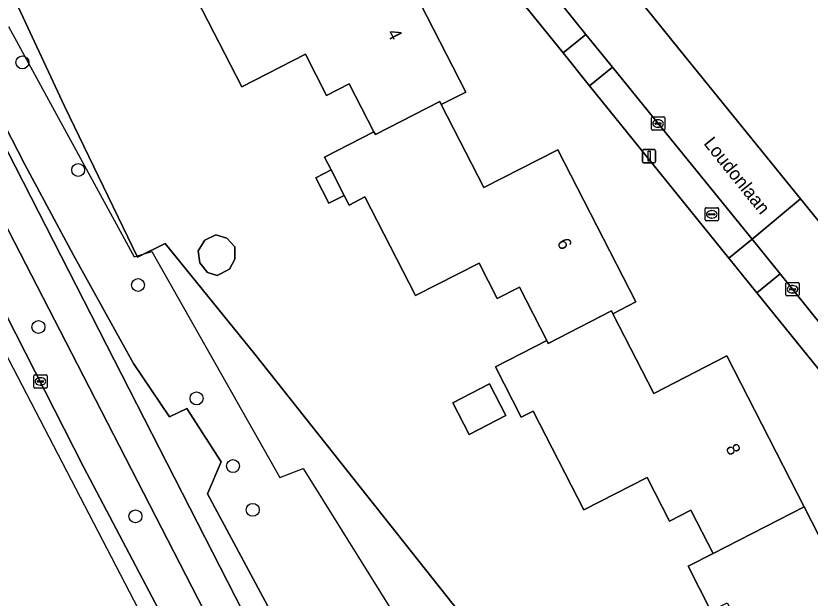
# Model space of a CAD drawing. Extents: x 162722 to 165104, y 384719 to 386284.
# Drawn here: x 163645.7 to 163705.8, y 384849.4 to 384893.4 of the extents above; entities that cross this region are included whole.
import ezdxf

# ---------------------------------------------------------------- set-up
doc = ezdxf.new("R2010")
doc.units = 0
for name, color, linetype in [('IMGEO_Berm_groen', 7, 'Continuous'), ('IMGEO_Boom', 7, 'Continuous'), ('IMGEO_Brandkraan', 7, 'Continuous'), ('IMGEO_Erf', 7, 'Continuous'), ('IMGEO_Fietspad_gesloten', 7, 'Continuous'), ('IMGEO_Hek', 7, 'Continuous'), ('IMGEO_Kolk', 7, 'Continuous'), ('IMGEO_Lichtmast', 7, 'Continuous'), ('IMGEO_Openbare_ruimte_label', 7, 'Continuous'), ('IMGEO_Pand', 7, 'Continuous'), ('IMGEO_Pand_nummerreeks', 7, 'Continuous'), ('IMGEO_Rijbaan_lokaal_gesloten', 7, 'Continuous'), ('IMGEO_Rijbaan_lokaal_open', 7, 'Continuous'), ('IMGEO_Voetpad_open', 7, 'Continuous')]:
    doc.layers.add(name, color=color, linetype=linetype)

msp = doc.modelspace()

# ---------------------------------------------------------------- linework, layer by layer
at = {"layer": 'IMGEO_Berm_groen'}
for points in [[(163618.626, 384922.554), (163650.793, 384859.299), (163659.712, 384842.417), (163662.889, 384836.994), (163664.818, 384838.033)], [(163638.999, 384898.509), (163639.887, 384894.801), (163646.367, 384882.192), (163650.033, 384875.332), (163654.583, 384867.14), (163657.311, 384863.103), (163658.611, 384863.729), (163661.225, 384859.68), (163660.178, 384857.261), (163662.179, 384853.562), (163665.659, 384847.064), (163668.571, 384839.571), (163668.894, 384837.227), (163669.249, 384836.772), (163671.885, 384838.65), (163674.113, 384840.236), (163675.569, 384841.273), (163677.65, 384842.757), (163681.501, 384845.463), (163663.771, 384867.845), (163656.977, 384876.206), (163654.894, 384875.166), (163649.374, 384886.592), (163636.133, 384914.976)], [(163633.056, 384906.66), (163665.701, 384842.782), (163667.32, 384839.609), (163671.35, 384831.709), (163674.979, 384824.942), (163683.91, 384808.691), (163686.492, 384803.504), (163689.41, 384798.303), (163693.89, 384789.977), (163696.466, 384785.483), (163698.828, 384781.441), (163701.216, 384777.578), (163702.109, 384776.133), (163703.848, 384773.319), (163706.839, 384768.481), (163708.537, 384765.733), (163719.206, 384748.466), (163719.245, 384748.398), (163720.867, 384749.354), (163706.656, 384772.239), (163699.71, 384783.423), (163697.853, 384786.61), (163685.147, 384809.788), (163673.174, 384831.928)], [(163665.107, 384838.393), (163664.91, 384838.757), (163649.896, 384867.932), (163630.013, 384906.502)], [(163673.174, 384831.928), (163673.157, 384831.926), (163673.03, 384831.916), (163669.249, 384836.772), (163668.894, 384837.227), (163668.571, 384839.571), (163665.659, 384847.064), (163662.179, 384853.562), (163660.178, 384857.261), (163661.225, 384859.68), (163658.611, 384863.729), (163657.311, 384863.103), (163654.583, 384867.14), (163650.033, 384875.332), (163646.367, 384882.192), (163639.887, 384894.801), (163638.999, 384898.509)]]:
    msp.add_lwpolyline(points, dxfattribs=at)
at = {"layer": 'IMGEO_Boom'}
for centre in [(163646.18, 384889.913), (163650.398, 384881.774), (163654.926, 384873.073), (163647.394, 384869.891), (163659.354, 384864.487), (163662.111, 384859.364), (163663.606, 384856.056), (163654.732, 384855.565)]:
    msp.add_circle(centre, 0.489, dxfattribs=at)
at = {"layer": 'IMGEO_Brandkraan'}
for p, q in [((163697.906, 384878.919), (163698.758, 384878.919)), ((163697.831, 384877.993), (163697.831, 384878.845)), ((163698.09, 384878.413), (163698.09, 384878.425)), ((163698.528, 384878.376), (163698.13, 384878.376)), ((163698.133, 384878.462), (163698.531, 384878.462)), ((163698.319, 384878.699), (163698.344, 384878.699)), ((163698.574, 384878.425), (163698.574, 384878.413)), ((163698.832, 384878.845), (163698.832, 384877.993)), ((163698.758, 384877.919), (163697.906, 384877.919)), ((163698.342, 384878.139), (163698.317, 384878.139))]:
    msp.add_line(p, q, dxfattribs=at)
for points in [[(163697.906, 384878.919), (163698.758, 384878.919)], [(163697.831, 384877.993), (163697.831, 384878.845)], [(163698.832, 384878.845), (163698.832, 384877.993)], [(163698.758, 384877.919), (163697.906, 384877.919)]]:
    msp.add_lwpolyline(points, dxfattribs=at)
for centre, radius, start, end in [((163697.908, 384878.843), 0.0765, 91.55205, 178.44795), ((163697.908, 384878.843), 0.0765, 91.55205, 178.44795), ((163698.756, 384878.843), 0.0765, 1.55205, 88.44795), ((163698.756, 384878.843), 0.0765, 1.55205, 88.44795), ((163698.13, 384878.422), 0.0403, 85.87752, 175.75265), ((163698.127, 384878.412), 0.0366, 178.93798, 274.71019), ((163698.531, 384878.419), 0.043, 264.86636, 352.45326), ((163698.535, 384878.424), 0.0386, 1.73085, 96.63898), ((163697.908, 384877.995), 0.0765, 181.55205, 268.44795), ((163697.908, 384877.995), 0.0765, 181.55205, 268.44795), ((163698.756, 384877.995), 0.0765, 271.55205, 358.44795), ((163698.756, 384877.995), 0.0765, 271.55205, 358.44795)]:
    msp.add_arc(centre, radius, start, end, dxfattribs=at)
for centre, major_axis, ratio, start_param, end_param in [((163698.318, 384878.419), (-0.387, 0.002), 0.722429, 4.712389, 7.853982), ((163698.343, 384878.419), (-0.39, 0.002), 0.717154, 1.570796, 4.712389)]:
    msp.add_ellipse(centre, major_axis=major_axis, ratio=ratio, start_param=start_param, end_param=end_param, dxfattribs=at)
at = {"layer": 'IMGEO_Erf'}
for points in [[(163689.085, 384888.134), (163687.084, 384890.632), (163676.468, 384903.753), (163673.969, 384906.848), (163673.753, 384907.134), (163665.55, 384917.268), (163665.421, 384917.261), (163660.75, 384923.114), (163663.751, 384924.681), (163669.399, 384920.052), (163676.37, 384925.254), (163699.363, 384942.796), (163694.404, 384952.9), (163692.876, 384955.959), (163685.319, 384971.004), (163683.732, 384974.099), (163682.29, 384976.876), (163639.563, 384955.061), (163635.539, 384952.364), (163633.451, 384950.624), (163627.464, 384944.399)], [(163626.969, 384940.192), (163627.34, 384939.051), (163629.221, 384933.258), (163631.785, 384926.085), (163636.133, 384914.976), (163649.374, 384886.592), (163654.894, 384875.166), (163656.977, 384876.206), (163663.771, 384867.845), (163681.501, 384845.463), (163682.422, 384844.301), (163682.516, 384843.215), (163683.525, 384843.812)], [(163643.226, 384914.296), (163652.091, 384918.839), (163655.38, 384912.42), (163660.955, 384915.277), (163666.893, 384903.689), (163664.992, 384902.715), (163668.281, 384896.297), (163673.843, 384899.147), (163679.724, 384887.671), (163677.87, 384886.721), (163681.088, 384880.442), (163686.682, 384883.309), (163692.585, 384871.79), (163690.85, 384870.9), (163693.941, 384864.866), (163699.469, 384867.698), (163705.313, 384856.295), (163708.601, 384849.88)], [(163679.55, 384911.309), (163688.362, 384900.411), (163688.262, 384900.349), (163695.837, 384890.93), (163705.052, 384879.586), (163719.232, 384862.132), (163726.729, 384852.876)], [(163698.271, 384848.404), (163696.535, 384851.79), (163698.425, 384852.759), (163696.748, 384856.031), (163695.135, 384855.204), (163693.44, 384858.512), (163688.643, 384856.054), (163684.816, 384863.522), (163683.918, 384863.062), (163681.97, 384866.865), (163685.861, 384868.859), (163683.785, 384872.908), (163682.106, 384872.048), (163680.733, 384874.727), (163675.924, 384872.263), (163672.094, 384879.736), (163670.889, 384879.119), (163670.515, 384879.849), (163669.367, 384879.261), (163668.38, 384881.187), (163669.528, 384881.775), (163669.026, 384882.754), (163672.764, 384884.669), (163670.908, 384888.292), (163669.186, 384887.41), (163667.585, 384890.535), (163662.779, 384888.072), (163658.953, 384895.538)], [(163712.454, 384859.238), (163701.751, 384872.467), (163699.616, 384875.107), (163689.085, 384888.134)]]:
    msp.add_lwpolyline(points, dxfattribs=at)
for points in [[(163662.253, 384875.962), (163662.261, 384875.022), (163661.859, 384874.271), (163660.916, 384873.801), (163660.177, 384874.004), (163659.6, 384874.736), (163659.473, 384875.65), (163659.981, 384876.466), (163660.817, 384876.858), (163661.649, 384876.601)], [(163682.74, 384863.185), (163679.965, 384861.763), (163678.738, 384864.159), (163681.513, 384865.581)]]:
    msp.add_lwpolyline(points, close=True, dxfattribs=at)
at = {"layer": 'IMGEO_Fietspad_gesloten'}
for points in [[(163665.701, 384842.782), (163633.056, 384906.66)], [(163630.013, 384906.502), (163649.896, 384867.932), (163664.91, 384838.757), (163665.107, 384838.393), (163666.456, 384835.906), (163666.58, 384835.676)]]:
    msp.add_lwpolyline(points, dxfattribs=at)
at = {"layer": 'IMGEO_Hek'}
msp.add_lwpolyline([(163645.13, 384892.627), (163654.624, 384875.189), (163655.97, 384875.609), (163665.663, 384858.504), (163667.411, 384859.184), (163677.65, 384842.757)], dxfattribs=at)
at = {"layer": 'IMGEO_Kolk'}
for p, q in [((163693.77, 384884.862), (163693.77, 384885.714)), ((163693.845, 384885.788), (163694.697, 384885.788)), ((163694.258, 384885.568), (163694.283, 384885.568)), ((163694.771, 384885.714), (163694.771, 384884.862)), ((163694.029, 384885.282), (163694.029, 384885.294)), ((163694.467, 384885.245), (163694.069, 384885.245)), ((163694.072, 384885.331), (163694.47, 384885.331)), ((163694.281, 384885.008), (163694.256, 384885.008)), ((163694.513, 384885.294), (163694.513, 384885.282)), ((163694.697, 384884.788), (163693.845, 384884.788)), ((163703.94, 384872.323), (163703.94, 384873.175)), ((163704.015, 384873.249), (163704.867, 384873.249)), ((163704.428, 384873.029), (163704.453, 384873.029)), ((163704.941, 384873.175), (163704.941, 384872.323)), ((163704.199, 384872.743), (163704.199, 384872.755)), ((163704.637, 384872.706), (163704.239, 384872.706)), ((163704.242, 384872.792), (163704.64, 384872.792)), ((163704.451, 384872.469), (163704.426, 384872.469)), ((163704.683, 384872.755), (163704.683, 384872.743)), ((163704.867, 384872.249), (163704.015, 384872.249)), ((163647.04, 384865.346), (163647.04, 384866.198)), ((163647.115, 384866.272), (163647.967, 384866.272)), ((163647.299, 384865.766), (163647.299, 384865.778)), ((163647.737, 384865.729), (163647.339, 384865.729)), ((163647.342, 384865.815), (163647.74, 384865.815)), ((163647.528, 384866.052), (163647.553, 384866.052)), ((163647.783, 384865.778), (163647.783, 384865.766)), ((163648.041, 384866.198), (163648.041, 384865.346)), ((163647.967, 384865.272), (163647.115, 384865.272)), ((163647.551, 384865.492), (163647.526, 384865.492))]:
    msp.add_line(p, q, dxfattribs=at)
for points in [[(163693.77, 384884.862), (163693.77, 384885.714)], [(163693.845, 384885.788), (163694.697, 384885.788)], [(163694.771, 384885.714), (163694.771, 384884.862)], [(163694.697, 384884.788), (163693.845, 384884.788)], [(163703.94, 384872.323), (163703.94, 384873.175)], [(163704.015, 384873.249), (163704.867, 384873.249)], [(163704.941, 384873.175), (163704.941, 384872.323)], [(163704.867, 384872.249), (163704.015, 384872.249)], [(163647.04, 384865.346), (163647.04, 384866.198)], [(163647.115, 384866.272), (163647.967, 384866.272)], [(163648.041, 384866.198), (163648.041, 384865.346)], [(163647.967, 384865.272), (163647.115, 384865.272)]]:
    msp.add_lwpolyline(points, dxfattribs=at)
for centre, radius, start, end in [((163693.847, 384885.712), 0.0765, 91.55205, 178.44795), ((163693.847, 384885.712), 0.0765, 91.55205, 178.44795), ((163694.695, 384885.712), 0.0765, 1.55205, 88.44795), ((163694.695, 384885.712), 0.0765, 1.55205, 88.44795), ((163694.069, 384885.291), 0.0403, 85.87752, 175.75265), ((163694.066, 384885.281), 0.0366, 178.93798, 274.71019), ((163694.47, 384885.288), 0.043, 264.86636, 352.45326), ((163694.474, 384885.293), 0.0386, 1.73085, 96.63898), ((163693.847, 384884.864), 0.0765, 181.55205, 268.44795), ((163693.847, 384884.864), 0.0765, 181.55205, 268.44795), ((163694.695, 384884.864), 0.0765, 271.55205, 358.44795), ((163694.695, 384884.864), 0.0765, 271.55205, 358.44795), ((163704.017, 384873.173), 0.0765, 91.55205, 178.44795), ((163704.017, 384873.173), 0.0765, 91.55205, 178.44795), ((163704.865, 384873.173), 0.0765, 1.55205, 88.44795), ((163704.865, 384873.173), 0.0765, 1.55205, 88.44795), ((163704.017, 384872.325), 0.0765, 181.55205, 268.44795), ((163704.017, 384872.325), 0.0765, 181.55205, 268.44795), ((163704.239, 384872.752), 0.0403, 85.87752, 175.75265), ((163704.236, 384872.742), 0.0366, 178.93798, 274.71019), ((163704.64, 384872.749), 0.043, 264.86636, 352.45326), ((163704.644, 384872.754), 0.0386, 1.73085, 96.63898), ((163704.865, 384872.325), 0.0765, 271.55205, 358.44795), ((163704.865, 384872.325), 0.0765, 271.55205, 358.44795), ((163647.117, 384866.196), 0.0765, 91.55205, 178.44795), ((163647.117, 384866.196), 0.0765, 91.55205, 178.44795), ((163647.339, 384865.775), 0.0403, 85.87752, 175.75265), ((163647.336, 384865.765), 0.0366, 178.93798, 274.71019), ((163647.74, 384865.772), 0.043, 264.86636, 352.45326), ((163647.744, 384865.777), 0.0386, 1.73085, 96.63898), ((163647.965, 384866.196), 0.0765, 1.55205, 88.44795), ((163647.965, 384866.196), 0.0765, 1.55205, 88.44795), ((163647.117, 384865.348), 0.0765, 181.55205, 268.44795), ((163647.117, 384865.348), 0.0765, 181.55205, 268.44795), ((163647.965, 384865.348), 0.0765, 271.55205, 358.44795), ((163647.965, 384865.348), 0.0765, 271.55205, 358.44795)]:
    msp.add_arc(centre, radius, start, end, dxfattribs=at)
for centre, major_axis, ratio, start_param, end_param in [((163694.257, 384885.288), (-0.387, 0.002), 0.722429, 4.712389, 7.853982), ((163694.282, 384885.288), (-0.39, 0.002), 0.717154, 1.570796, 4.712389), ((163704.427, 384872.749), (-0.387, 0.002), 0.722429, 4.712389, 7.853982), ((163704.452, 384872.749), (-0.39, 0.002), 0.717154, 1.570796, 4.712389), ((163647.527, 384865.772), (-0.387, 0.002), 0.722429, 4.712389, 7.853982), ((163647.552, 384865.772), (-0.39, 0.002), 0.717154, 1.570796, 4.712389)]:
    msp.add_ellipse(centre, major_axis=major_axis, ratio=ratio, start_param=start_param, end_param=end_param, dxfattribs=at)
at = {"layer": 'IMGEO_Lichtmast'}
for p, q in [((163693.091, 384882.411), (163693.091, 384883.211)), ((163693.091, 384883.211), (163693.091, 384882.411)), ((163693.191, 384883.311), (163693.981, 384883.311)), ((163693.981, 384883.311), (163693.191, 384883.311)), ((163694.081, 384883.211), (163694.081, 384882.411)), ((163694.081, 384882.411), (163694.081, 384883.211)), ((163693.981, 384882.311), (163693.191, 384882.311)), ((163693.191, 384882.311), (163693.981, 384882.311))]:
    msp.add_line(p, q, dxfattribs=at)
msp.add_lwpolyline([(163693.511, 384883.186), (163693.661, 384883.186), (163693.661, 384882.436), (163693.511, 384882.436), (163693.511, 384883.186)], dxfattribs=at)
for centre, start, end in [((163693.191, 384883.211), 90, 180), ((163693.191, 384883.211), 90, 180), ((163693.981, 384883.211), 0, 90), ((163693.981, 384883.211), 360, 90), ((163693.191, 384882.411), 180, 270), ((163693.191, 384882.411), 180, 270), ((163693.981, 384882.411), 270, 0), ((163693.981, 384882.411), 270, 0)]:
    msp.add_arc(centre, 0.1, start, end, dxfattribs=at)
at = {"layer": 'IMGEO_Pand'}
for points in [[(163672.764, 384884.669), (163672.879, 384884.447), (163677.755, 384886.944), (163677.87, 384886.721), (163679.724, 384887.671), (163673.843, 384899.147), (163668.281, 384896.297), (163664.992, 384902.715), (163664.897, 384902.897), (163660.018, 384900.398), (163659.924, 384900.579), (163656.021, 384898.578), (163657.864, 384894.981), (163658.953, 384895.538), (163662.779, 384888.072), (163667.585, 384890.535), (163669.186, 384887.41), (163670.908, 384888.292)], [(163686.682, 384883.309), (163681.088, 384880.442), (163677.87, 384886.721), (163677.755, 384886.944), (163672.879, 384884.447), (163672.764, 384884.669), (163669.026, 384882.754), (163669.528, 384881.775), (163670.515, 384879.849), (163670.889, 384879.119), (163672.094, 384879.736), (163675.924, 384872.263), (163680.733, 384874.727), (163682.106, 384872.048), (163683.785, 384872.908), (163685.861, 384868.859), (163685.965, 384868.654), (163690.745, 384871.106), (163690.85, 384870.9), (163692.585, 384871.79)], [(163669.528, 384881.775), (163668.38, 384881.187), (163669.367, 384879.261), (163670.515, 384879.849)], [(163661.649, 384876.601), (163660.817, 384876.858), (163659.981, 384876.466), (163659.473, 384875.65), (163659.6, 384874.736), (163660.177, 384874.004), (163660.916, 384873.801), (163661.859, 384874.271), (163662.261, 384875.022), (163662.253, 384875.962)], [(163698.425, 384852.759), (163705.313, 384856.295), (163699.469, 384867.698), (163693.941, 384864.866), (163690.85, 384870.9), (163690.745, 384871.106), (163685.965, 384868.654), (163685.861, 384868.859), (163681.97, 384866.865), (163683.918, 384863.062), (163684.816, 384863.522), (163688.643, 384856.054), (163693.44, 384858.512), (163695.135, 384855.204), (163696.748, 384856.031)], [(163678.738, 384864.159), (163679.965, 384861.763), (163682.74, 384863.185), (163681.513, 384865.581)], [(163713.273, 384837.99), (163713.401, 384837.744), (163717.196, 384839.688), (163717.322, 384839.444), (163720.439, 384841.041), (163714.389, 384852.846), (163708.601, 384849.88), (163705.313, 384856.295), (163698.425, 384852.759), (163696.535, 384851.79), (163698.271, 384848.404), (163699.491, 384849.029), (163703.261, 384841.671), (163708.008, 384844.104), (163709.682, 384840.837), (163711.371, 384841.703)]]:
    msp.add_lwpolyline(points, close=True, dxfattribs=at)
at = {"layer": 'IMGEO_Rijbaan_lokaal_gesloten'}
for points in [[(163615.167, 384931.135), (163614.715, 384932.593), (163613.318, 384931.873), (163619.127, 384917.491), (163661.347, 384836.226)], [(163661.347, 384836.226), (163662.889, 384836.994), (163659.712, 384842.417), (163650.793, 384859.299), (163618.626, 384922.554)]]:
    msp.add_lwpolyline(points, dxfattribs=at)
at = {"layer": 'IMGEO_Rijbaan_lokaal_open'}
for points in [[(163674.367, 384909.96), (163675.679, 384908.261), (163678.232, 384905.132), (163684.328, 384897.597), (163688.814, 384892.037), (163690.833, 384889.565), (163694.271, 384885.288), (163701.376, 384876.543), (163705.052, 384879.586), (163695.837, 384890.93), (163688.262, 384900.349), (163688.362, 384900.411), (163679.55, 384911.309)], [(163726.729, 384852.876), (163719.232, 384862.132), (163705.052, 384879.586), (163701.376, 384876.543), (163703.517, 384873.907), (163704.441, 384872.749), (163713.909, 384860.955), (163714.201, 384860.638), (163715.953, 384858.469), (163721.534, 384851.578), (163724.495, 384847.949)]]:
    msp.add_lwpolyline(points, dxfattribs=at)
at = {"layer": 'IMGEO_Voetpad_open'}
for points in [[(163684.328, 384897.597), (163678.232, 384905.132), (163676.468, 384903.753), (163687.084, 384890.632), (163688.814, 384892.037)], [(163688.814, 384892.037), (163687.084, 384890.632), (163689.085, 384888.134), (163690.833, 384889.565)], [(163694.271, 384885.288), (163690.833, 384889.565), (163689.085, 384888.134), (163699.616, 384875.107), (163701.376, 384876.543)], [(163701.376, 384876.543), (163699.616, 384875.107), (163701.751, 384872.467), (163703.517, 384873.907)], [(163713.909, 384860.955), (163704.441, 384872.749), (163703.517, 384873.907), (163701.751, 384872.467), (163712.454, 384859.238), (163714.201, 384860.638)]]:
    msp.add_lwpolyline(points, close=True, dxfattribs=at)

# ---------------------------------------------------------------- texts
at = {"layer": 'IMGEO_Openbare_ruimte_label'}
msp.add_text('Loudonlaan', height=1, rotation=308.74928, dxfattribs=at).set_placement((163697.666, 384883.77))
at = {"layer": 'IMGEO_Pand_nummerreeks'}
for s, rotation, p in [('4', 297.13336, (163673.739, 384892.157)), ('6', 297.13507, (163686.589, 384876.299)), ('8', 297.13499, (163699.348, 384860.742))]:
    msp.add_text(s, height=1, rotation=rotation, dxfattribs=at).set_placement(p)

doc.saveas('drawing.dxf')
